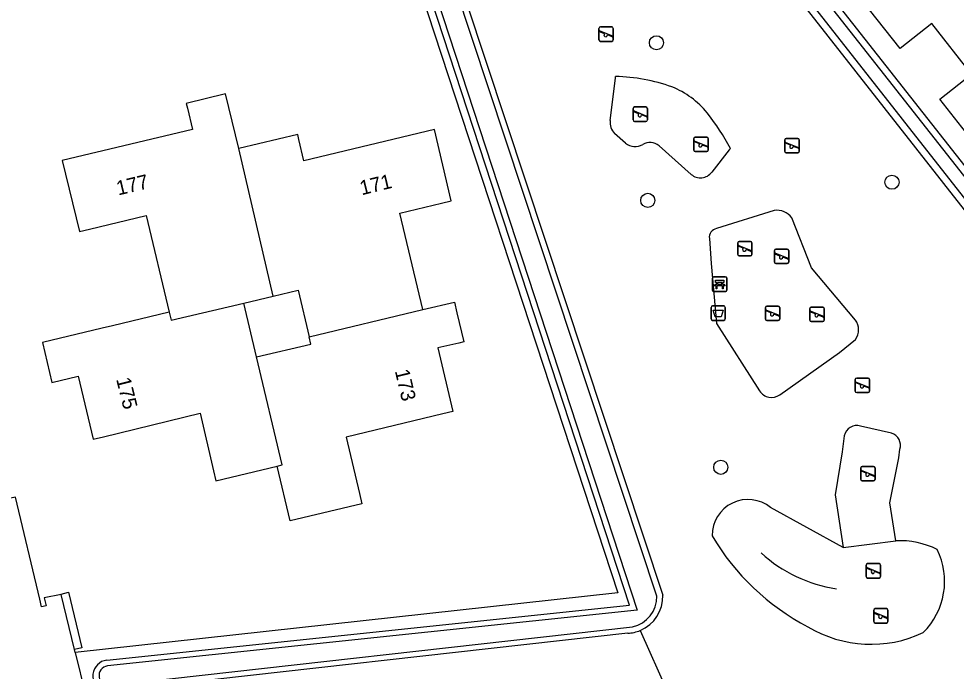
# Model space of a CAD drawing. Extents: x 156664 to 157568, y 383571 to 384421.
# Drawn here: x 156959.8 to 157024.8, y 383937.7 to 383982.9 of the extents above; entities that cross this region are included whole.
import ezdxf

# ---------------------------------------------------------------- set-up
doc = ezdxf.new("R2010")
doc.units = 0
for name, color, linetype in [('IMGEO_Afvalbak', 7, 'Continuous'), ('IMGEO_Bank', 7, 'Continuous'), ('IMGEO_Boom', 7, 'Continuous'), ('IMGEO_Groenvoorziening', 7, 'Continuous'), ('IMGEO_Hek', 7, 'Continuous'), ('IMGEO_Muur', 7, 'Continuous'), ('IMGEO_Pand', 7, 'Continuous'), ('IMGEO_Pand_nummerreeks', 7, 'Continuous'), ('IMGEO_Rijbaan_lokaal_open', 7, 'Continuous'), ('IMGEO_Speelvoorziening', 7, 'Continuous'), ('IMGEO_Waterloop', 7, 'Continuous')]:
    doc.layers.add(name, color=color, linetype=linetype)

msp = doc.modelspace()

# ---------------------------------------------------------------- linework, layer by layer
at = {"layer": 'IMGEO_Afvalbak'}
for p, q in [((157007.774, 383962.134), (157007.774, 383962.934)), ((157007.774, 383962.934), (157007.774, 383962.134)), ((157007.874, 383963.034), (157008.664, 383963.034)), ((157008.664, 383963.034), (157007.874, 383963.034)), ((157008.764, 383962.934), (157008.764, 383962.134)), ((157008.764, 383962.134), (157008.764, 383962.934)), ((157008.664, 383962.034), (157007.874, 383962.034)), ((157007.874, 383962.034), (157008.664, 383962.034))]:
    msp.add_line(p, q, dxfattribs=at)
msp.add_lwpolyline([(157007.917, 383962.748), (157008.621, 383962.748), (157008.472, 383962.278), (157008.066, 383962.278), (157007.917, 383962.748)], dxfattribs=at)
for centre, start, end in [((157007.874, 383962.934), 90, 180), ((157007.874, 383962.934), 90, 180), ((157008.664, 383962.934), 0, 90), ((157008.664, 383962.934), 360, 90), ((157007.874, 383962.134), 180, 270), ((157007.874, 383962.134), 180, 270), ((157008.664, 383962.134), 270, 0), ((157008.664, 383962.134), 270, 0)]:
    msp.add_arc(centre, 0.1, start, end, dxfattribs=at)
at = {"layer": 'IMGEO_Bank'}
for p, q in [((157007.872, 383964.112), (157007.872, 383964.953)), ((157007.872, 383964.953), (157007.872, 383964.112)), ((157007.947, 383965.037), (157008.788, 383965.037)), ((157008.788, 383965.037), (157007.947, 383965.037)), ((157008.872, 383964.962), (157008.872, 383964.121)), ((157008.872, 383964.121), (157008.872, 383964.962)), ((157008.569, 383964.435), (157008.176, 383964.435)), ((157008.181, 383964.543), (157008.181, 383964.649)), ((157008.225, 383964.649), (157008.225, 383964.543)), ((157008.513, 383964.655), (157008.231, 383964.655)), ((157008.231, 383964.537), (157008.513, 383964.537)), ((157008.519, 383964.543), (157008.519, 383964.649)), ((157008.563, 383964.649), (157008.563, 383964.543)), ((157008.797, 383964.037), (157007.956, 383964.037)), ((157007.956, 383964.037), (157008.797, 383964.037))]:
    msp.add_line(p, q, dxfattribs=at)
for points in [[(157008.175, 383964.655), (157008.089, 383964.655), (157008.089, 383964.816), (157008.652, 383964.816), (157008.652, 383964.655), (157008.569, 383964.655)], [(157008.119, 383964.435), (157007.977, 383964.435), (157008.089, 383964.537), (157008.175, 383964.537)], [(157008.169, 383964.428), (157008.169, 383964.221), (157008.126, 383964.221), (157008.126, 383964.428)], [(157008.569, 383964.537), (157008.652, 383964.537), (157008.764, 383964.435), (157008.625, 383964.435)], [(157008.619, 383964.428), (157008.619, 383964.221), (157008.575, 383964.221), (157008.575, 383964.428)]]:
    msp.add_lwpolyline(points, dxfattribs=at)
for centre, radius, start, end in [((157007.95, 383964.959), 0.0779, 92.4484, 184.28452), ((157007.95, 383964.959), 0.0779, 92.4484, 184.28452), ((157008.794, 383964.959), 0.0779, 2.4484, 94.28452), ((157008.794, 383964.959), 0.0779, 2.4484, 94.28452), ((157007.95, 383964.115), 0.0779, 182.4484, 274.28452), ((157007.95, 383964.115), 0.0779, 182.4484, 274.28452), ((157008.119, 383964.428), 0.00671, 2.89567, 87.10433), ((157008.176, 383964.428), 0.00671, 92.89567, 177.10433), ((157008.174, 383964.648), 0.00671, 2.89567, 87.10433), ((157008.174, 383964.544), 0.00671, 272.89567, 357.10433), ((157008.231, 383964.648), 0.00671, 92.89567, 177.10433), ((157008.231, 383964.544), 0.00671, 182.89567, 267.10433), ((157008.513, 383964.648), 0.00671, 2.89567, 87.10433), ((157008.513, 383964.544), 0.00671, 272.89567, 357.10433), ((157008.57, 383964.648), 0.00671, 92.89567, 177.10433), ((157008.57, 383964.544), 0.00671, 182.89567, 267.10433), ((157008.568, 383964.428), 0.00671, 2.89567, 87.10433), ((157008.625, 383964.428), 0.00671, 92.89567, 177.10433), ((157008.794, 383964.115), 0.0779, 272.4484, 4.28452), ((157008.794, 383964.115), 0.0779, 272.4484, 4.28452)]:
    msp.add_arc(centre, radius, start, end, dxfattribs=at)
at = {"layer": 'IMGEO_Boom'}
for centre in [(157003.99, 383981.261), (157020.31, 383971.6), (157003.391, 383970.345), (157008.45, 383951.855)]:
    msp.add_circle(centre, 0.489, dxfattribs=at)
at = {"layer": 'IMGEO_Groenvoorziening'}
for points in [[(156976.265, 384037.915), (156976.159, 384036.79), (156978.828, 384029.096), (156978.106, 384028.607), (156979.057, 384027.27), (156979.971, 384027.441), (156999.575, 384002.48), (157046.243, 383943.057), (157049.143, 383939.851), (157051.199, 383938.08), (157065.553, 383939.239), (157066.12, 383939.807), (157065.473, 383940.297), (157051.572, 383939.133), (157050.688, 383940.493), (157046.683, 383945.676), (157001.17, 384003.466), (156980.256, 384030.02)], [(156965.9, 383938.498), (157002.117, 383942.318), (156972.167, 384033.813), (156964.844, 384031.779), (156863.418, 384007.321)], [(156974.445, 384033.505), (156979.934, 384016.935), (157004.429, 383942.995)], [(156953.099, 383937.896), (156882.007, 383929.988), (156863.465, 384006.689), (156971.911, 384032.865), (156984.848, 383993.384), (157001.305, 383943.16), (156963.71, 383939.037)], [(157059.17, 383949.866), (157058.574, 383949.397), (157057.089, 383951.283), (157054.795, 383949.476), (157051.268, 383953.956), (157047.773, 383951.203), (157044.246, 383955.682), (157042.046, 383953.95), (157037.729, 383959.435), (157039.929, 383961.167), (157037.195, 383964.64), (157034.995, 383962.908), (157030.678, 383968.393), (157032.878, 383970.125), (157030.144, 383973.598), (157027.944, 383971.866), (157023.627, 383977.351), (157025.827, 383979.082), (157023.068, 383982.587), (157020.868, 383980.855), (157016.54, 383986.353)], [(157000.785, 383975.878), (157001.148, 383978.803), (157001.163, 383978.927)], [(157001.857, 383974.31), (157001.093, 383974.975)], [(157006.403, 383972.141), (157004.174, 383974.126)], [(157009.115, 383973.94), (157009.038, 383973.843), (157007.823, 383972.296)], [(157012.149, 383969.639), (157008.154, 383968.391)], [(157017.778, 383962.053), (157014.738, 383965.678), (157013.367, 383969.124)], [(157007.665, 383967.697), (157007.785, 383965.975), (157008.158, 383961.806), (157011.133, 383957.145)], [(157012.542, 383956.866), (157016.666, 383959.816), (157017.778, 383960.716)], [(157020.276, 383954.231), (157018.138, 383954.715)], [(157017.006, 383954.029), (157016.86, 383952.918), (157016.372, 383949.946), (157016.921, 383946.31)], [(157020.576, 383946.768), (157020.173, 383949.396), (157020.795, 383952.507), (157020.864, 383953.103)], [(157016.921, 383946.31), (157011.9, 383949.065)], [(157016.921, 383946.31), (157020.576, 383946.768)], [(157002.005, 383940.362), (156966.194, 383936.347)], [(157002.87, 383940.558), (157004.772, 383936.263)]]:
    msp.add_lwpolyline(points, dxfattribs=at)
for centre, radius, start, end in [((157000.806, 383966.164), 12.768, 70.51838, 88.39665), ((157002.861, 383972.642), 5.98, 38.98762, 68.38289), ((156995.067, 383966.539), 15.879, 27.78176, 38.4097), ((157001.821, 383975.727), 1.047, 171.7222, 225.9453), ((157002.51, 383975.053), 0.989, 228.69424, 302.30821), ((157003.542, 383973.368), 0.987, 50.18986, 120.64224), ((157007.042, 383972.872), 0.97, 228.83758, 323.62133), ((157012.348, 383968.412), 1.243, 34.94143, 99.21893), ((157008.254, 383967.802), 0.598, 99.59043, 190.07168), ((157016.886, 383961.385), 1.115, 323.15837, 36.84163), ((157011.976, 383957.704), 1.011, 213.5555, 304.04368), ((157017.882, 383953.861), 0.892, 73.3182, 169.11412), ((157019.99, 383953.364), 0.913, 343.35252, 71.71144), ((157010.327, 383947.145), 2.482, 50.67213, 180.69254), ((157022.248, 383955.637), 16.735, 210.61129, 242.37077), ((157020.818, 383940.736), 6.037, 64.1542, 92.29967), ((157018.959, 383943.965), 5.003, 314.68379, 26.14329), ((157001.886, 383942.904), 2.544, 292.74539, 2.03881), ((157018.858, 383948.091), 8.493, 239.01989, 295.21954), ((157001.884, 383942.904), 2.545, 272.73093, 292.80316), ((156966.024, 383937.419), 1.086, 96.54358, 251.04485)]:
    msp.add_arc(centre, radius, start, end, dxfattribs=at)
at = {"layer": 'IMGEO_Hek'}
for points in [[(156953.099, 383937.896), (156882.007, 383929.988), (156863.465, 384006.689), (156971.911, 384032.865), (156984.848, 383993.384), (157001.305, 383943.16)], [(157001.305, 383943.16), (156963.71, 383939.037)]]:
    msp.add_lwpolyline(points, dxfattribs=at)
at = {"layer": 'IMGEO_Muur'}
for points in [[(156961.383, 383942.196), (156961.258, 383942.72)], [(156962.748, 383943.053), (156962.741, 383943.079), (156963.264, 383943.206), (156964.173, 383939.363), (156963.662, 383939.235)], [(156963.662, 383939.235), (156962.748, 383943.053)], [(156961.704, 383942.271), (156961.383, 383942.196)]]:
    msp.add_lwpolyline(points, dxfattribs=at)
msp.add_arc((157017.871, 383953.124), 9.778, 227.44031, 261.68178, dxfattribs=at)
at = {"layer": 'IMGEO_Pand'}
for points in [[(156975.06, 383973.932), (156974.137, 383977.717), (156971.415, 383977.062), (156971.504, 383976.722), (156971.852, 383975.263), (156962.825, 383973.112), (156964.014, 383968.177), (156964.699, 383968.344), (156968.628, 383969.298), (156970.235, 383962.605)], [(156987.808, 383962.783), (156986.213, 383969.465), (156989.088, 383970.151), (156989.777, 383970.317), (156988.618, 383975.257), (156979.558, 383973.088), (156979.223, 383974.559), (156979.145, 383974.9), (156975.06, 383973.932)], [(156977.442, 383963.708), (156975.06, 383973.932)], [(156977.442, 383963.708), (156979.175, 383964.117), (156979.936, 383960.895)], [(156975.409, 383963.228), (156977.442, 383963.708)], [(156970.235, 383962.605), (156970.369, 383962.049), (156975.409, 383963.228)], [(156976.289, 383959.499), (156975.409, 383963.228)], [(156987.808, 383962.783), (156989.993, 383963.295), (156990.169, 383962.548), (156990.641, 383960.543), (156990.301, 383960.462), (156988.84, 383960.119), (156989.886, 383955.727), (156989.184, 383955.552), (156982.49, 383953.946), (156983.418, 383950.037), (156983.576, 383949.323), (156978.611, 383948.146), (156977.705, 383951.93)], [(156979.936, 383960.895), (156987.808, 383962.783)], [(156970.235, 383962.605), (156966.308, 383961.654), (156965.598, 383961.482), (156961.445, 383960.502), (156962.099, 383957.733), (156963.92, 383958.163), (156964.957, 383953.811), (156965.671, 383953.972), (156972.366, 383955.602), (156973.306, 383951.616), (156973.468, 383950.93), (156977.705, 383951.93)], [(156976.289, 383959.499), (156980.055, 383960.388), (156979.936, 383960.895)], [(156977.705, 383951.93), (156978.063, 383952.018), (156976.289, 383959.499)]]:
    msp.add_lwpolyline(points, dxfattribs=at)
at = {"layer": 'IMGEO_Rijbaan_lokaal_open'}
for points in [[(156962.748, 383943.053), (156961.579, 383942.807), (156961.704, 383942.271), (156961.383, 383942.196), (156961.258, 383942.72), (156959.573, 383949.776), (156954.882, 383948.869), (156956.564, 383941.597), (156956.615, 383941.611), (156956.745, 383941.083)], [(156963.71, 383939.037), (156963.662, 383939.235)], [(156963.71, 383939.037), (156964.423, 383936.119)]]:
    msp.add_lwpolyline(points, dxfattribs=at)
at = {"layer": 'IMGEO_Speelvoorziening'}
for p, q in [((157000.009, 383981.458), (157000.009, 383982.258)), ((157000.009, 383982.258), (157000.009, 383981.458)), ((157000.109, 383982.358), (157000.899, 383982.358)), ((157000.899, 383982.358), (157000.109, 383982.358)), ((157000.999, 383982.258), (157000.999, 383981.458)), ((157000.999, 383981.458), (157000.999, 383982.258)), ((157000.392, 383981.886), (157000.053, 383982.023)), ((157000.078, 383982.083), (157000.954, 383981.73)), ((157000.93, 383981.67), (157000.59, 383981.807)), ((157000.899, 383981.358), (157000.109, 383981.358)), ((157000.109, 383981.358), (157000.899, 383981.358)), ((157002.375, 383975.911), (157002.375, 383976.711)), ((157002.375, 383976.711), (157002.375, 383975.911)), ((157002.758, 383976.339), (157002.419, 383976.476)), ((157002.444, 383976.536), (157003.32, 383976.183)), ((157002.475, 383976.811), (157003.265, 383976.811)), ((157003.265, 383976.811), (157002.475, 383976.811)), ((157003.365, 383976.711), (157003.365, 383975.911)), ((157003.365, 383975.911), (157003.365, 383976.711)), ((157003.265, 383975.811), (157002.475, 383975.811)), ((157002.475, 383975.811), (157003.265, 383975.811)), ((157003.296, 383976.123), (157002.956, 383976.26)), ((157006.583, 383973.829), (157006.583, 383974.629)), ((157006.583, 383974.629), (157006.583, 383973.829)), ((157006.652, 383974.454), (157007.528, 383974.101)), ((157006.683, 383974.729), (157007.473, 383974.729)), ((157007.473, 383974.729), (157006.683, 383974.729)), ((157007.573, 383974.629), (157007.573, 383973.829)), ((157007.573, 383973.829), (157007.573, 383974.629)), ((157012.887, 383973.737), (157012.887, 383974.537)), ((157012.887, 383974.537), (157012.887, 383973.737)), ((157012.987, 383974.637), (157013.777, 383974.637)), ((157013.777, 383974.637), (157012.987, 383974.637)), ((157013.877, 383974.537), (157013.877, 383973.737)), ((157013.877, 383973.737), (157013.877, 383974.537)), ((157006.966, 383974.257), (157006.627, 383974.394)), ((157007.504, 383974.041), (157007.164, 383974.178)), ((157013.27, 383974.165), (157012.931, 383974.302)), ((157012.956, 383974.362), (157013.832, 383974.009)), ((157013.808, 383973.949), (157013.468, 383974.086)), ((157007.473, 383973.729), (157006.683, 383973.729)), ((157006.683, 383973.729), (157007.473, 383973.729)), ((157013.777, 383973.637), (157012.987, 383973.637)), ((157012.987, 383973.637), (157013.777, 383973.637)), ((157009.62, 383966.596), (157009.62, 383967.396)), ((157009.62, 383967.396), (157009.62, 383966.596)), ((157009.72, 383967.496), (157010.51, 383967.496)), ((157010.51, 383967.496), (157009.72, 383967.496)), ((157010.61, 383967.396), (157010.61, 383966.596)), ((157010.61, 383966.596), (157010.61, 383967.396)), ((157010.003, 383967.024), (157009.664, 383967.161)), ((157009.689, 383967.221), (157010.565, 383966.868)), ((157010.541, 383966.808), (157010.201, 383966.945)), ((157012.164, 383966.061), (157012.164, 383966.861)), ((157012.164, 383966.861), (157012.164, 383966.061)), ((157012.233, 383966.686), (157013.109, 383966.333)), ((157012.264, 383966.961), (157013.054, 383966.961)), ((157013.054, 383966.961), (157012.264, 383966.961)), ((157013.154, 383966.861), (157013.154, 383966.061)), ((157013.154, 383966.061), (157013.154, 383966.861)), ((157010.51, 383966.496), (157009.72, 383966.496)), ((157009.72, 383966.496), (157010.51, 383966.496)), ((157012.547, 383966.489), (157012.208, 383966.626)), ((157013.085, 383966.273), (157012.745, 383966.41)), ((157013.054, 383965.961), (157012.264, 383965.961)), ((157012.264, 383965.961), (157013.054, 383965.961)), ((157011.542, 383962.119), (157011.542, 383962.919)), ((157011.542, 383962.919), (157011.542, 383962.119)), ((157011.611, 383962.744), (157012.487, 383962.391)), ((157011.642, 383963.019), (157012.432, 383963.019)), ((157012.432, 383963.019), (157011.642, 383963.019)), ((157012.532, 383962.919), (157012.532, 383962.119)), ((157012.532, 383962.119), (157012.532, 383962.919)), ((157014.623, 383962.046), (157014.623, 383962.846)), ((157014.623, 383962.846), (157014.623, 383962.046)), ((157014.723, 383962.946), (157015.513, 383962.946)), ((157015.513, 383962.946), (157014.723, 383962.946)), ((157015.613, 383962.846), (157015.613, 383962.046)), ((157015.613, 383962.046), (157015.613, 383962.846)), ((157011.925, 383962.547), (157011.586, 383962.684)), ((157012.463, 383962.331), (157012.123, 383962.468)), ((157015.006, 383962.474), (157014.667, 383962.611)), ((157014.692, 383962.671), (157015.568, 383962.318)), ((157015.544, 383962.258), (157015.204, 383962.395)), ((157012.432, 383962.019), (157011.642, 383962.019)), ((157011.642, 383962.019), (157012.432, 383962.019)), ((157015.513, 383961.946), (157014.723, 383961.946)), ((157014.723, 383961.946), (157015.513, 383961.946)), ((157017.766, 383957.137), (157017.766, 383957.937)), ((157017.766, 383957.937), (157017.766, 383957.137)), ((157018.149, 383957.565), (157017.81, 383957.702)), ((157017.835, 383957.762), (157018.711, 383957.409)), ((157017.866, 383958.037), (157018.656, 383958.037)), ((157018.656, 383958.037), (157017.866, 383958.037)), ((157018.756, 383957.937), (157018.756, 383957.137)), ((157018.756, 383957.137), (157018.756, 383957.937)), ((157018.656, 383957.037), (157017.866, 383957.037)), ((157017.866, 383957.037), (157018.656, 383957.037)), ((157018.687, 383957.349), (157018.347, 383957.486)), ((157018.15, 383951.015), (157018.15, 383951.815)), ((157018.15, 383951.815), (157018.15, 383951.015)), ((157018.25, 383951.915), (157019.04, 383951.915)), ((157019.04, 383951.915), (157018.25, 383951.915)), ((157019.14, 383951.815), (157019.14, 383951.015)), ((157019.14, 383951.015), (157019.14, 383951.815)), ((157018.533, 383951.443), (157018.194, 383951.58)), ((157018.219, 383951.64), (157019.095, 383951.287)), ((157019.071, 383951.227), (157018.731, 383951.364)), ((157019.04, 383950.915), (157018.25, 383950.915)), ((157018.25, 383950.915), (157019.04, 383950.915)), ((157018.526, 383944.284), (157018.526, 383945.084)), ((157018.526, 383945.084), (157018.526, 383944.284)), ((157018.909, 383944.712), (157018.57, 383944.849)), ((157018.595, 383944.909), (157019.471, 383944.556)), ((157018.626, 383945.184), (157019.416, 383945.184)), ((157019.416, 383945.184), (157018.626, 383945.184)), ((157019.447, 383944.496), (157019.107, 383944.633)), ((157019.516, 383945.084), (157019.516, 383944.284)), ((157019.516, 383944.284), (157019.516, 383945.084)), ((157019.416, 383944.184), (157018.626, 383944.184)), ((157018.626, 383944.184), (157019.416, 383944.184)), ((157019.045, 383941.17), (157019.045, 383941.97)), ((157019.045, 383941.97), (157019.045, 383941.17)), ((157019.145, 383942.07), (157019.935, 383942.07)), ((157019.935, 383942.07), (157019.145, 383942.07)), ((157020.035, 383941.97), (157020.035, 383941.17)), ((157020.035, 383941.17), (157020.035, 383941.97)), ((157019.428, 383941.598), (157019.089, 383941.735)), ((157019.114, 383941.795), (157019.99, 383941.442)), ((157019.966, 383941.382), (157019.626, 383941.519)), ((157019.935, 383941.07), (157019.145, 383941.07)), ((157019.145, 383941.07), (157019.935, 383941.07))]:
    msp.add_line(p, q, dxfattribs=at)
for centre, radius, start, end in [((157000.109, 383982.258), 0.1, 90, 180), ((157000.109, 383982.258), 0.1, 90, 180), ((157000.899, 383982.258), 0.1, 0, 90), ((157000.899, 383982.258), 0.1, 360, 90), ((157000.066, 383982.053), 0.0327, 68.07798, 248.07798), ((157000.471, 383981.796), 0.12, 130.99278, 5.16318), ((157000.942, 383981.7), 0.0327, 248.07798, 68.07798), ((157000.109, 383981.458), 0.1, 180, 270), ((157000.109, 383981.458), 0.1, 180, 270), ((157000.899, 383981.458), 0.1, 270, 0), ((157000.899, 383981.458), 0.1, 270, 0), ((157002.475, 383976.711), 0.1, 90, 180), ((157002.475, 383976.711), 0.1, 90, 180), ((157002.432, 383976.506), 0.0327, 68.07798, 248.07798), ((157003.265, 383976.711), 0.1, 0, 90), ((157003.265, 383976.711), 0.1, 360, 90), ((157002.475, 383975.911), 0.1, 180, 270), ((157002.475, 383975.911), 0.1, 180, 270), ((157002.837, 383976.249), 0.12, 130.99278, 5.16318), ((157003.265, 383975.911), 0.1, 270, 0), ((157003.265, 383975.911), 0.1, 270, 0), ((157003.308, 383976.153), 0.0327, 248.07798, 68.07798), ((157006.683, 383974.629), 0.1, 90, 180), ((157006.683, 383974.629), 0.1, 90, 180), ((157006.64, 383974.424), 0.0327, 68.07798, 248.07798), ((157007.473, 383974.629), 0.1, 0, 90), ((157007.473, 383974.629), 0.1, 360, 90), ((157012.987, 383974.537), 0.1, 90, 180), ((157012.987, 383974.537), 0.1, 90, 180), ((157013.777, 383974.537), 0.1, 0, 90), ((157013.777, 383974.537), 0.1, 360, 90), ((157006.683, 383973.829), 0.1, 180, 270), ((157006.683, 383973.829), 0.1, 180, 270), ((157007.045, 383974.167), 0.12, 130.99278, 5.16318), ((157007.473, 383973.829), 0.1, 270, 0), ((157007.473, 383973.829), 0.1, 270, 0), ((157007.516, 383974.071), 0.0327, 248.07798, 68.07798), ((157012.944, 383974.332), 0.0327, 68.07798, 248.07798), ((157013.349, 383974.075), 0.12, 130.99278, 5.16318), ((157013.82, 383973.979), 0.0327, 248.07798, 68.07798), ((157012.987, 383973.737), 0.1, 180, 270), ((157012.987, 383973.737), 0.1, 180, 270), ((157013.777, 383973.737), 0.1, 270, 0), ((157013.777, 383973.737), 0.1, 270, 0), ((157009.72, 383967.396), 0.1, 90, 180), ((157009.72, 383967.396), 0.1, 90, 180), ((157010.51, 383967.396), 0.1, 0, 90), ((157010.51, 383967.396), 0.1, 360, 90), ((157009.677, 383967.191), 0.0327, 68.07798, 248.07798), ((157010.082, 383966.934), 0.12, 130.99278, 5.16318), ((157010.553, 383966.838), 0.0327, 248.07798, 68.07798), ((157012.264, 383966.861), 0.1, 90, 180), ((157012.264, 383966.861), 0.1, 90, 180), ((157012.221, 383966.656), 0.0327, 68.07798, 248.07798), ((157013.054, 383966.861), 0.1, 0, 90), ((157013.054, 383966.861), 0.1, 360, 90), ((157009.72, 383966.596), 0.1, 180, 270), ((157009.72, 383966.596), 0.1, 180, 270), ((157010.51, 383966.596), 0.1, 270, 0), ((157010.51, 383966.596), 0.1, 270, 0), ((157012.264, 383966.061), 0.1, 180, 270), ((157012.264, 383966.061), 0.1, 180, 270), ((157012.626, 383966.399), 0.12, 130.99278, 5.16318), ((157013.054, 383966.061), 0.1, 270, 0), ((157013.054, 383966.061), 0.1, 270, 0), ((157013.097, 383966.303), 0.0327, 248.07798, 68.07798), ((157011.642, 383962.919), 0.1, 90, 180), ((157011.642, 383962.919), 0.1, 90, 180), ((157011.599, 383962.714), 0.0327, 68.07798, 248.07798), ((157012.432, 383962.919), 0.1, 0, 90), ((157012.432, 383962.919), 0.1, 360, 90), ((157014.723, 383962.846), 0.1, 90, 180), ((157014.723, 383962.846), 0.1, 90, 180), ((157015.513, 383962.846), 0.1, 0, 90), ((157015.513, 383962.846), 0.1, 360, 90), ((157011.642, 383962.119), 0.1, 180, 270), ((157011.642, 383962.119), 0.1, 180, 270), ((157012.004, 383962.457), 0.12, 130.99278, 5.16318), ((157012.432, 383962.119), 0.1, 270, 0), ((157012.432, 383962.119), 0.1, 270, 0), ((157012.475, 383962.361), 0.0327, 248.07798, 68.07798), ((157014.68, 383962.641), 0.0327, 68.07798, 248.07798), ((157015.085, 383962.384), 0.12, 130.99278, 5.16318), ((157015.556, 383962.288), 0.0327, 248.07798, 68.07798), ((157014.723, 383962.046), 0.1, 180, 270), ((157014.723, 383962.046), 0.1, 180, 270), ((157015.513, 383962.046), 0.1, 270, 0), ((157015.513, 383962.046), 0.1, 270, 0), ((157017.866, 383957.937), 0.1, 90, 180), ((157017.866, 383957.937), 0.1, 90, 180), ((157017.823, 383957.732), 0.0327, 68.07798, 248.07798), ((157018.228, 383957.475), 0.12, 130.99278, 5.16318), ((157018.656, 383957.937), 0.1, 0, 90), ((157018.656, 383957.937), 0.1, 360, 90), ((157017.866, 383957.137), 0.1, 180, 270), ((157017.866, 383957.137), 0.1, 180, 270), ((157018.656, 383957.137), 0.1, 270, 0), ((157018.656, 383957.137), 0.1, 270, 0), ((157018.699, 383957.379), 0.0327, 248.07798, 68.07798), ((157018.25, 383951.815), 0.1, 90, 180), ((157018.25, 383951.815), 0.1, 90, 180), ((157019.04, 383951.815), 0.1, 0, 90), ((157019.04, 383951.815), 0.1, 360, 90), ((157018.207, 383951.61), 0.0327, 68.07798, 248.07798), ((157018.612, 383951.353), 0.12, 130.99278, 5.16318), ((157019.083, 383951.257), 0.0327, 248.07798, 68.07798), ((157018.25, 383951.015), 0.1, 180, 270), ((157018.25, 383951.015), 0.1, 180, 270), ((157019.04, 383951.015), 0.1, 270, 0), ((157019.04, 383951.015), 0.1, 270, 0), ((157018.626, 383945.084), 0.1, 90, 180), ((157018.626, 383945.084), 0.1, 90, 180), ((157018.583, 383944.879), 0.0327, 68.07798, 248.07798), ((157018.988, 383944.622), 0.12, 130.99278, 5.16318), ((157019.416, 383945.084), 0.1, 0, 90), ((157019.416, 383945.084), 0.1, 360, 90), ((157019.459, 383944.526), 0.0327, 248.07798, 68.07798), ((157018.626, 383944.284), 0.1, 180, 270), ((157018.626, 383944.284), 0.1, 180, 270), ((157019.416, 383944.284), 0.1, 270, 0), ((157019.416, 383944.284), 0.1, 270, 0), ((157019.145, 383941.97), 0.1, 90, 180), ((157019.145, 383941.97), 0.1, 90, 180), ((157019.935, 383941.97), 0.1, 0, 90), ((157019.935, 383941.97), 0.1, 360, 90), ((157019.102, 383941.765), 0.0327, 68.07798, 248.07798), ((157019.507, 383941.508), 0.12, 130.99278, 5.16318), ((157019.978, 383941.412), 0.0327, 248.07798, 68.07798), ((157019.145, 383941.17), 0.1, 180, 270), ((157019.145, 383941.17), 0.1, 180, 270), ((157019.935, 383941.17), 0.1, 270, 0), ((157019.935, 383941.17), 0.1, 270, 0)]:
    msp.add_arc(centre, radius, start, end, dxfattribs=at)
at = {"layer": 'IMGEO_Waterloop'}
for points in [[(156863.303, 384007.711), (156964.742, 384032.172), (156972.432, 384034.308), (157002.659, 383941.967), (156965.949, 383938.095)], [(157004.025, 383942.925), (156979.576, 384016.724), (156979.549, 384016.807), (156973.994, 384033.587)], [(157000.774, 384003.154), (157028.774, 383967.601)], [(157028.661, 383966.26), (157028.063, 383967.022), (156999.971, 384002.791)], [(156966.143, 383936.75), (157002.336, 383940.813)]]:
    msp.add_lwpolyline(points, dxfattribs=at)
for centre, radius, start, end in [((157001.885, 383942.905), 2.14, 282.16745, 0.53279), ((156966.047, 383937.423), 0.679, 98.25538, 278.15986)]:
    msp.add_arc(centre, radius, start, end, dxfattribs=at)

# ---------------------------------------------------------------- texts
at = {"layer": 'IMGEO_Pand_nummerreeks'}
for s, rotation, p in [('177', 13.20841, (156966.698, 383970.681)), ('171', 13.67621, (156983.569, 383970.695)), ('173', 283.38769, (156985.86, 383958.532)), ('175', 284.03122, (156966.55, 383957.959))]:
    msp.add_text(s, height=1, rotation=rotation, dxfattribs=at).set_placement(p)

doc.saveas('drawing.dxf')
